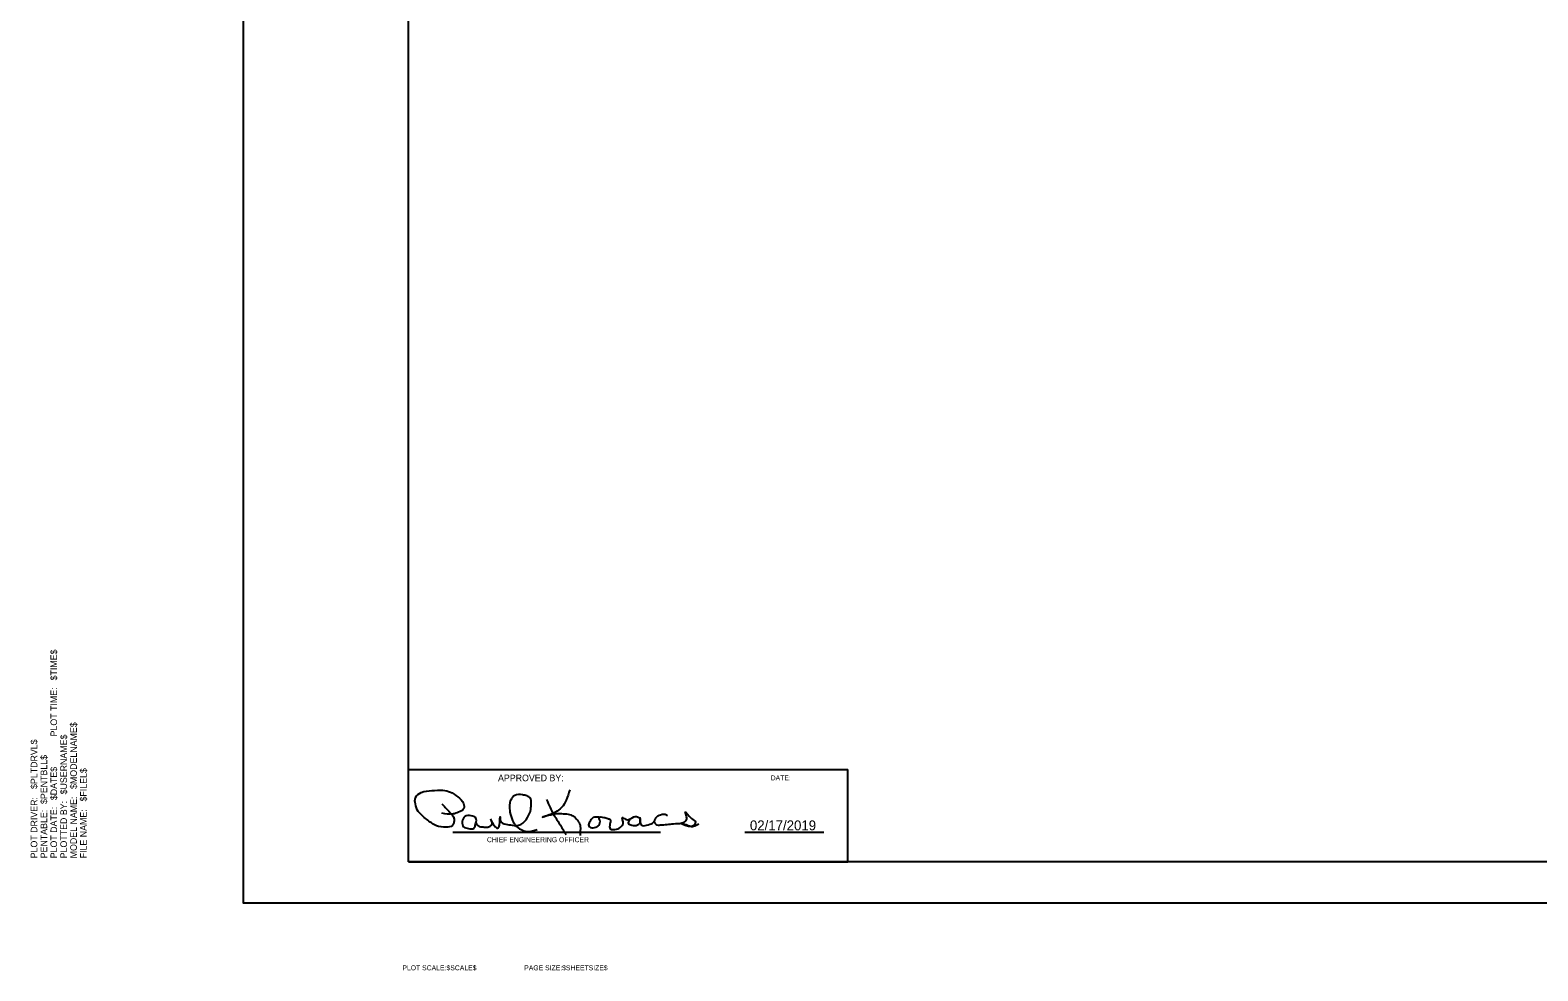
# Model space of a CAD drawing. Extents: x -0.22 to 2.83, y -0.07 to 1.83.
# Drawn here: x -0.216 to 1.309, y -0.068 to 0.882 of the extents above; entities that cross this region are included whole.
import ezdxf

# ---------------------------------------------------------------- set-up
doc = ezdxf.new("R2010")
doc.units = 0
for name, color, linetype in [('SH_General_Details', 7, 'Continuous'), ('SH_General_Details_Signature-ILTollway', 7, 'Continuous'), ('SH_Printer Plotting Border-ILTollway', 7, 'Continuous'), ('SH_Variables-ILTollway', 7, 'Continuous')]:
    doc.layers.add(name, color=color, linetype=linetype)

msp = doc.modelspace()

# ---------------------------------------------------------------- linework, layer by layer
at = {"layer": 'SH_General_Details'}
msp.add_lwpolyline([(0.1667, 0.0417), (0.1667, 1.7917), (2.7917, 1.7917), (2.7917, 0.0417)], close=True, dxfattribs=at)
at = {"layer": 'SH_General_Details_Signature-ILTollway'}
for p, q in [((0.1667, 0.1352), (0.6111, 0.1352)), ((0.6111, 0.0417), (0.6111, 0.1352)), ((0.2117, 0.0717), (0.4217, 0.0717)), ((0.5067, 0.0717), (0.5867, 0.0717)), ((0.1667, 0.0417), (0.6111, 0.0417))]:
    msp.add_line(p, q, dxfattribs=at)
for points in [[(0.2004, 0.1006), (0.2077, 0.0929), (0.2129, 0.085), (0.2112, 0.0785), (0.2047, 0.0768), (0.195, 0.0783), (0.1851, 0.0848), (0.1767, 0.0928), (0.1737, 0.1003), (0.1739, 0.1068), (0.1795, 0.1119), (0.1904, 0.1139), (0.2016, 0.1142), (0.2091, 0.1124), (0.2165, 0.1076), (0.2224, 0.1007), (0.2226, 0.0958), (0.2174, 0.092), (0.212, 0.0902), (0.2004, 0.0909)], [(0.2497, 0.085), (0.2538, 0.0781), (0.257, 0.076), (0.2585, 0.0779), (0.259, 0.0825), (0.2595, 0.0873), (0.2598, 0.0834), (0.2651, 0.08), (0.2715, 0.0789), (0.2802, 0.0796), (0.287, 0.0866), (0.2905, 0.095), (0.2907, 0.1011), (0.2901, 0.1063), (0.2866, 0.1084), (0.2819, 0.1095), (0.2743, 0.109), (0.2702, 0.1043), (0.269, 0.0994), (0.2694, 0.0919), (0.2721, 0.0837), (0.2748, 0.0788), (0.2808, 0.0744), (0.2861, 0.0726), (0.2923, 0.0731), (0.297, 0.0746)], [(0.3298, 0.1147), (0.3262, 0.1041), (0.3216, 0.0967), (0.3153, 0.092), (0.3065, 0.0884), (0.3025, 0.0872), (0.3152, 0.0904), (0.3232, 0.0905), (0.3297, 0.0897), (0.3339, 0.0876), (0.3385, 0.0826), (0.3405, 0.0777), (0.3403, 0.0719), (0.3402, 0.0686)], [(0.3063, 0.1049), (0.31, 0.0967), (0.3134, 0.0898), (0.3196, 0.0802), (0.3227, 0.0749), (0.3261, 0.0696)], [(0.4152, 0.0824), (0.4171, 0.0796), (0.4214, 0.0791), (0.4283, 0.0796), (0.4348, 0.0804), (0.4431, 0.0811), (0.4475, 0.0836), (0.448, 0.0872), (0.4467, 0.0921), (0.453, 0.0858), (0.4569, 0.0818), (0.4546, 0.0782), (0.4474, 0.0791), (0.4427, 0.0805), (0.4499, 0.078), (0.4549, 0.0779), (0.4604, 0.0804)], [(0.2351, 0.0808), (0.2349, 0.086), (0.2303, 0.0884), (0.2238, 0.0876), (0.2211, 0.0825), (0.2224, 0.0773), (0.2274, 0.0755), (0.2328, 0.0757), (0.2343, 0.0786), (0.2348, 0.0812), (0.2369, 0.0785), (0.2422, 0.0771), (0.2469, 0.0769), (0.2502, 0.0785), (0.2514, 0.0804), (0.2497, 0.085)], [(0.3595, 0.0869), (0.3534, 0.0865), (0.35, 0.0823), (0.3491, 0.0781), (0.3509, 0.0764), (0.3563, 0.077), (0.3593, 0.0788), (0.3602, 0.084), (0.3595, 0.0866), (0.3642, 0.0868), (0.3682, 0.0857), (0.3707, 0.0844), (0.3705, 0.0798), (0.3707, 0.0753), (0.3739, 0.0745), (0.3798, 0.076), (0.3835, 0.0795), (0.3836, 0.0834), (0.383, 0.0866), (0.3862, 0.0849), (0.3902, 0.0848), (0.396, 0.0876), (0.401, 0.0862)], [(0.3905, 0.0851), (0.3893, 0.0803), (0.3925, 0.0789), (0.3983, 0.0791), (0.4009, 0.0816), (0.401, 0.0862), (0.4012, 0.0806), (0.4033, 0.0786), (0.4091, 0.0794), (0.4146, 0.0819), (0.4169, 0.0864), (0.4217, 0.0895), (0.4275, 0.0894), (0.4286, 0.0887)]]:
    msp.add_spline(points, degree=3, dxfattribs=at)
at = {"layer": 'SH_Printer Plotting Border-ILTollway'}
msp.add_lwpolyline([(0, 1.8333), (2.8333, 1.8333), (2.8333, 0), (0, 0)], close=True, dxfattribs=at)

# ---------------------------------------------------------------- texts
at = {"layer": 'SH_General_Details_Signature-ILTollway'}
for s, height, p in [('APPROVED BY:', 0.006667, (0.2573, 0.1233)), ('DATE:', 0.005, (0.533, 0.1242)), ('CHIEF ENGINEERING OFFICER', 0.005, (0.2461, 0.0617))]:
    msp.add_text(s, height=height, rotation=0, dxfattribs=at).set_placement(p)
msp.add_text('02/17/2019', height=0.01, dxfattribs=at).set_placement((0.512, 0.0737))
at = {"layer": 'SH_Variables-ILTollway'}
for s, height, rotation, p in [('$TIME$', 0.00667, 90, (-0.1886, 0.2252)), ('PLOT TIME:', 0.00667, 90, (-0.1886, 0.1686)), ('$USERNAME$', 0.00667, 90, (-0.1786, 0.11)), ('$MODELNAME$', 0.006667, 90, (-0.1686, 0.1155)), ('$PLTDRVL$', 0.00667, 90, (-0.2086, 0.1155)), ('$PENTBLL$', 0.00667, 90, (-0.1986, 0.1003)), ('$DATE$', 0.00667, 90, (-0.1886, 0.1042)), ('$FILEL$', 0.00667, 90, (-0.1586, 0.1028)), ('MODEL NAME:', 0.006667, 90, (-0.1686, 0.0454)), ('PLOT DRIVER:', 0.006667, 90, (-0.2086, 0.0454)), ('PENTABLE:', 0.00667, 90, (-0.1986, 0.0454)), ('PLOT DATE:', 0.00667, 90, (-0.1886, 0.0454)), ('PLOTTED BY:', 0.006667, 90, (-0.1786, 0.0454)), ('FILE NAME:', 0.00667, 90, (-0.1586, 0.0454)), ('PLOT SCALE:', 0.005, 360, (0.1606, -0.0678)), ('$SCALE$', 0.005, 360, (0.2052, -0.0678)), ('PAGE SIZE:', 0.005, 360, (0.2838, -0.0678)), ('$SHEETSIZE$', 0.005, 360, (0.3221, -0.0678))]:
    msp.add_text(s, height=height, rotation=rotation, dxfattribs=at).set_placement(p)

doc.saveas('drawing.dxf')
